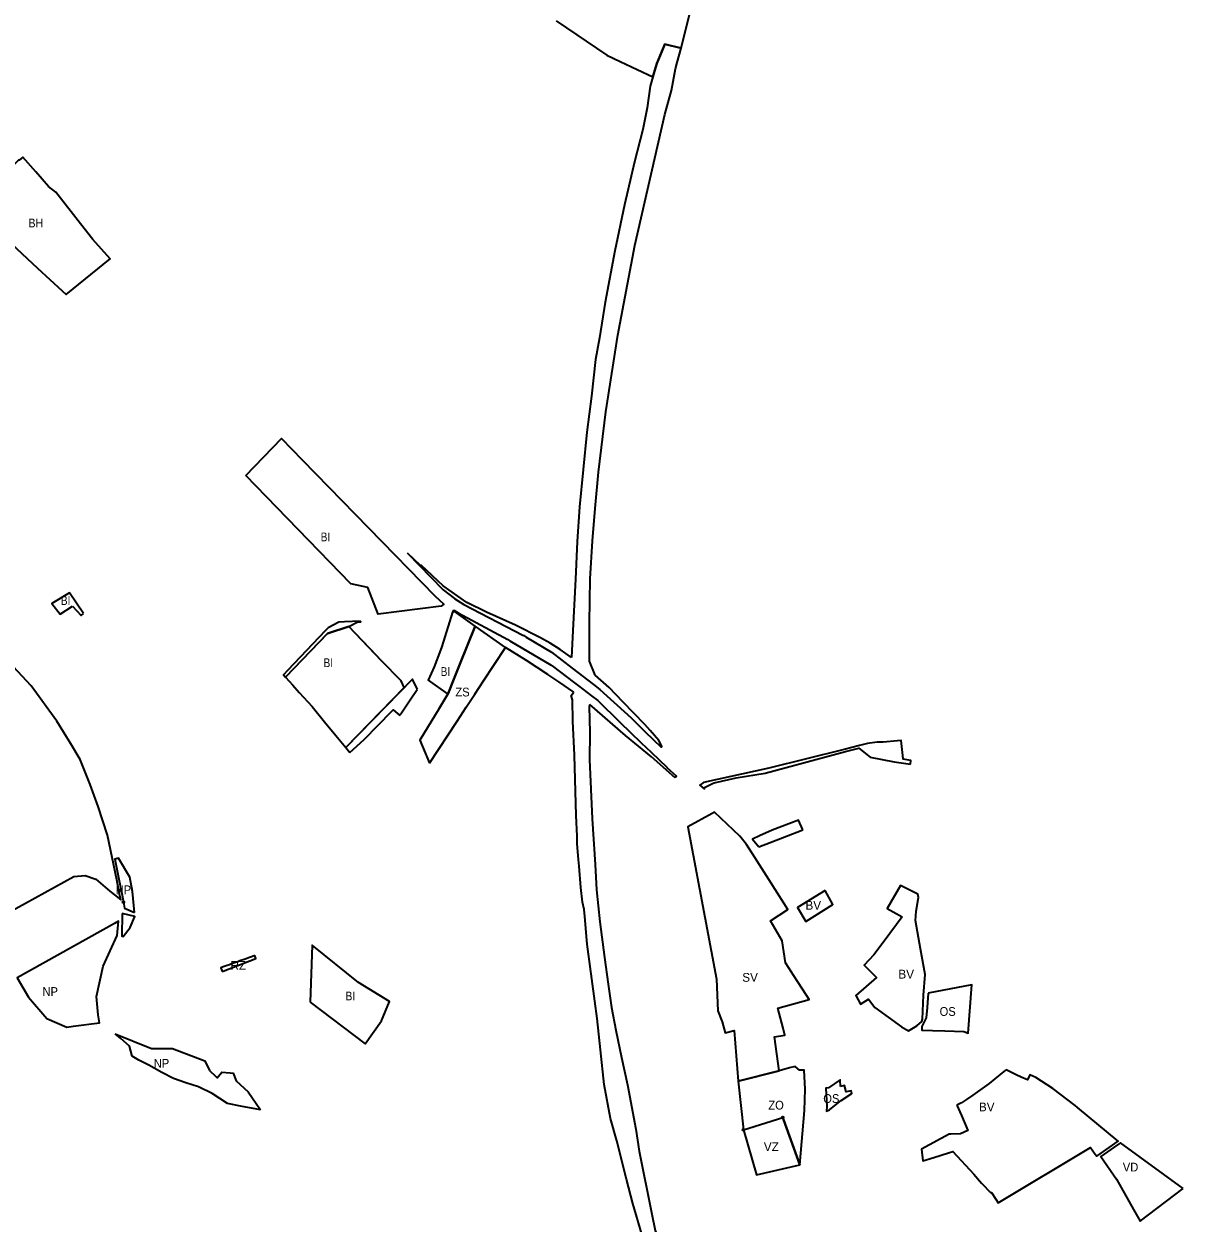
# Model space of a CAD drawing. Extents: x -650276 to -642489, y -1074311 to -1066658.
# Drawn here: x -646121 to -644537, y -1073213 to -1071573 of the extents above; entities that cross this region are included whole.
import ezdxf

# ---------------------------------------------------------------- set-up
doc = ezdxf.new("R2010")
doc.units = 0
doc.header["$LTSCALE"] = 4.8
doc.header["$PDMODE"] = 32
doc.header["$PDSIZE"] = 2.4
for name, color, linetype, lineweight in [('1', 7, 'Continuous', 35), ('15', 7, 'Continuous', 35), ('18', 7, 'Continuous', 35), ('2', 7, 'Continuous', 35), ('24', 7, 'Continuous', 35), ('3', 7, 'Continuous', 35), ('35', 7, 'Continuous', 35), ('36', 7, 'Continuous', 35), ('41', 7, 'Continuous', 35), ('42', 7, 'Continuous', 35), ('48', 7, 'Continuous', 35), ('6', 7, 'Continuous', 35), ('9', 7, 'Continuous', 35)]:
    doc.layers.add(name, color=color, linetype=linetype, lineweight=lineweight)
doc.layers.add('62', color=7, linetype='Continuous')
doc.layers.add('63', color=7, linetype='Continuous')

msp = doc.modelspace()

# ---------------------------------------------------------------- linework, layer by layer
at = {"layer": '1'}
msp.add_lwpolyline([(-646102.04, -1071906.4), (-646068.317, -1071937.555), (-646062.91, -1071942.55), (-646002.93, -1071893.984), (-646026.64, -1071867.44), (-646043.49, -1071845.87), (-646077.32, -1071802.59), (-646087, -1071795), (-646104.5, -1071774.86), (-646122.16, -1071754.78), (-646127.12, -1071759.15), (-646127.84, -1071758.53), (-646191.57, -1071821.44), (-646174.69, -1071838.69), (-646156.59, -1071856.53), (-646137.74, -1071873.31)], close=True, dxfattribs=at)
at = {"layer": '15'}
for points in [[(-645661.3, -1072388.74), (-645682.59, -1072389.76), (-645690.37, -1072390.13), (-645705, -1072398.19), (-645708.94, -1072402.11)], [(-645676.53, -1072396.16), (-645676.53, -1072396.16), (-645665.32, -1072390.32), (-645660.16, -1072389.95), (-645661.3, -1072388.74)], [(-645708.94, -1072402.11), (-645760.02, -1072455.94), (-645765.95, -1072462.03), (-645763.06, -1072465.26)], [(-645763.06, -1072465.26), (-645706.039, -1072405.769), (-645676.53, -1072396.16)], [(-645582.84, -1072481.71), (-645584.46, -1072478.58), (-645589.862, -1072468.109), (-645680.87, -1072561.42), (-645675.13, -1072568.36)], [(-645607.07, -1072517.61), (-645605.95, -1072515.95), (-645604.82, -1072514.3), (-645592.9, -1072496.52), (-645583.13, -1072482.13), (-645582.84, -1072481.71)], [(-645675.13, -1072568.36), (-645655.65, -1072550.62), (-645617.87, -1072512.12), (-645615.95, -1072510.16), (-645607.07, -1072517.61)], [(-644926.81, -1072552.51), (-644946.57, -1072554.22), (-644954.57, -1072554.43), (-644967.97, -1072556.17), (-644978.56, -1072558.74), (-644999.72, -1072564.24), (-645102.73, -1072589.74), (-645192.06, -1072609.19), (-645197.044, -1072612.821), (-645190.71, -1072618.6)], [(-644919.75, -1072572.43), (-644921.84, -1072552.03), (-644926.81, -1072552.51)], [(-645147.13, -1072602.79), (-645107.58, -1072596.47), (-644997.92, -1072567.23), (-644979.55, -1072562.44), (-644963.97, -1072574.57)], [(-644909.02, -1072584.28), (-644908.59, -1072579.51), (-644919.23, -1072577.46), (-644919.75, -1072572.43)], [(-644963.97, -1072574.57), (-644931.48, -1072581.26), (-644909.02, -1072584.28)], [(-645190.71, -1072618.6), (-645190.59, -1072616.28), (-645179.6, -1072610.94), (-645177.56, -1072609.89), (-645147.13, -1072602.79)], [(-645056.08, -1072674.07), (-645062.131, -1072660.856), (-645098.016, -1072674.425), (-645115.56, -1072682.406), (-645124.933, -1072686.721), (-645116.11, -1072697.15)], [(-645116.11, -1072697.15), (-645100.9, -1072691.31), (-645056.08, -1072674.07)]]:
    msp.add_lwpolyline(points, dxfattribs=at)
at = {"layer": '18'}
msp.add_lwpolyline([(-645144.37, -1073017.64), (-645088.62, -1073003.45), (-645095.04, -1072957.07), (-645080.61, -1072954.43), (-645083.13, -1072944.94), (-645090.34, -1072917.86), (-645047.42, -1072906.05), (-645050.6, -1072901.03), (-645069.55, -1072872.12), (-645071.87, -1072868.45), (-645079.81, -1072855.89), (-645084.47, -1072825.67), (-645100.27, -1072798.46), (-645076.66, -1072783.06), (-645099.58, -1072746.945), (-645121.96, -1072711.68), (-645133.26, -1072694.17), (-645142.1, -1072682.57), (-645176.757, -1072649.968), (-645180.05, -1072651.77), (-645213.34, -1072669.98), (-645174.13, -1072877.93), (-645172.28, -1072921.42), (-645166.48, -1072936.5), (-645162.379, -1072951.55), (-645149.84, -1072948.13)], close=True, dxfattribs=at)
at = {"layer": '2'}
msp.add_line((-645553.35, -1072508.1), (-645541.09, -1072487.98), dxfattribs=at)
for points in [[(-645817.219, -1072189.975), (-645768.649, -1072139.283), (-645740.45, -1072168.23), (-645559.34, -1072354.42), (-645546.82, -1072365.72), (-645550.41, -1072368.47), (-645636.37, -1072379.57), (-645650.78, -1072342.73), (-645674, -1072338), (-645789.298, -1072218.833)], [(-645729.36, -1072909.65), (-645654.16, -1072966.3), (-645632.23, -1072935.28), (-645620.92, -1072908.65), (-645663.52, -1072882.58), (-645726.9, -1072831.5)]]:
    msp.add_lwpolyline(points, close=True, dxfattribs=at)
for points in [[(-646039.16, -1072378.43), (-646058.64, -1072350.29), (-646082.55, -1072364.84), (-646071, -1072379.27), (-646054.43, -1072368.34)], [(-646054.43, -1072368.34), (-646042.65, -1072381.23), (-646039.16, -1072378.43)], [(-645541.09, -1072487.98), (-645533.15, -1072468.21), (-645524.87, -1072447.61), (-645503.98, -1072395.64), (-645532.75, -1072375.41), (-645535.05, -1072376.72), (-645549.6, -1072423.39), (-645551.54, -1072428.66), (-645559.92, -1072451.41), (-645568.38, -1072469.68), (-645541.56, -1072488.74)], [(-645632.1, -1072442.93), (-645676.53, -1072396.16), (-645706.039, -1072405.769), (-645763.06, -1072465.26), (-645753.128, -1072476.383), (-645744.38, -1072486.18), (-645726.95, -1072505.7), (-645709.92, -1072526.3), (-645694.51, -1072544.93), (-645680.87, -1072561.42), (-645600.883, -1072479.409)], [(-645632.1, -1072442.93), (-645638.82, -1072435.99), (-645676.53, -1072396.16), (-645706.039, -1072405.769), (-645763.06, -1072465.26), (-645753.128, -1072476.383)], [(-645600.945, -1072479.473), (-645605.17, -1072470.52), (-645632.1, -1072442.93)], [(-645753.128, -1072476.383), (-645744.38, -1072486.18), (-645726.95, -1072505.7), (-645709.92, -1072526.3)], [(-645709.92, -1072526.3), (-645694.51, -1072544.93), (-645680.87, -1072561.42), (-645600.945, -1072479.473)]]:
    msp.add_lwpolyline(points, dxfattribs=at)
at = {"layer": '24'}
for points in [[(-645393.34, -1071568.75), (-645324.17, -1071615.53), (-645324.17, -1071615.53), (-645305.78, -1071624.13), (-645282.54, -1071634.997), (-645261.094, -1071645.025), (-645255.662, -1071626.67), (-645248.786, -1071610.383), (-645244.81, -1071600.61), (-645222.48, -1071606.08), (-645222.48, -1071606.08), (-645211.27, -1071560.01)], [(-645222.48, -1071606.08), (-645244.81, -1071600.61), (-645248.786, -1071610.383), (-645255.662, -1071626.67)], [(-645222.48, -1071606.08), (-645244.81, -1071600.61), (-645248.786, -1071610.383), (-645255.662, -1071626.67)], [(-645339.904, -1072462.677), (-645347.551, -1072443.527), (-645347.677, -1072391.355), (-645346.62, -1072330.914), (-645343.458, -1072278.998), (-645339.908, -1072235.158), (-645335.367, -1072185.207), (-645325.498, -1072102.789), (-645309.01, -1071998.147), (-645285.617, -1071875.733), (-645244.798, -1071696.585), (-645235.793, -1071663.703), (-645230.436, -1071634.261), (-645227.905, -1071625.277), (-645222.48, -1071606.08)], [(-645339.904, -1072462.677), (-645347.551, -1072443.527), (-645347.677, -1072391.355), (-645346.62, -1072330.914), (-645343.458, -1072278.998), (-645339.908, -1072235.158), (-645335.367, -1072185.207), (-645325.498, -1072102.789), (-645309.01, -1071998.147), (-645285.617, -1071875.733), (-645244.798, -1071696.585), (-645235.793, -1071663.703), (-645230.436, -1071634.261), (-645227.905, -1071625.277), (-645222.48, -1071606.08)], [(-645255.662, -1071626.67), (-645261.094, -1071645.025), (-645264.841, -1071657.687), (-645269.077, -1071687.396), (-645274.868, -1071717.176), (-645286.175, -1071761.228), (-645300.076, -1071820.179), (-645313.153, -1071883.081), (-645326.343, -1071952.807)], [(-645255.662, -1071626.67), (-645261.094, -1071645.025), (-645264.841, -1071657.687), (-645269.077, -1071687.396), (-645274.868, -1071717.176), (-645286.175, -1071761.228), (-645300.076, -1071820.179), (-645313.153, -1071883.081)], [(-645313.153, -1071883.081), (-645326.343, -1071952.807), (-645334.118, -1072001.954), (-645339.455, -1072031.565), (-645344.819, -1072081.225), (-645351.358, -1072130.815), (-645361.317, -1072232.824), (-645364.435, -1072280.268), (-645366.951, -1072331.609), (-645370.624, -1072401.447), (-645372.228, -1072438.764)], [(-645326.343, -1071952.807), (-645334.118, -1072001.954), (-645339.455, -1072031.565), (-645344.819, -1072081.225), (-645351.358, -1072130.815), (-645361.317, -1072232.824), (-645364.435, -1072280.268), (-645366.951, -1072331.609), (-645370.624, -1072401.447), (-645372.228, -1072438.764)], [(-645372.228, -1072438.764), (-645387.894, -1072427.453), (-645401.441, -1072419.033), (-645414.631, -1072411.611), (-645448.831, -1072394.325), (-645488.64, -1072376.782), (-645515.437, -1072363.447), (-645547.593, -1072340.827), (-645577.33, -1072312.704), (-645579.217, -1072312.425), (-645596.405, -1072296.114)], [(-645596.405, -1072296.114), (-645564.4, -1072328.61), (-645547.72, -1072346.19), (-645532.07, -1072358.01), (-645531.65, -1072358.29), (-645528.27, -1072360.53), (-645519.57, -1072366.3), (-645438.64, -1072408.1)], [(-645372.228, -1072438.764), (-645387.894, -1072427.453), (-645401.441, -1072419.033), (-645414.631, -1072411.611), (-645448.831, -1072394.325), (-645488.64, -1072376.782), (-645515.437, -1072363.447), (-645547.593, -1072340.827), (-645577.33, -1072312.704), (-645579.217, -1072312.425), (-645596.405, -1072296.114)], [(-645596.405, -1072296.114), (-645564.4, -1072328.61), (-645547.72, -1072346.19), (-645532.07, -1072358.01), (-645531.65, -1072358.29), (-645528.27, -1072360.53), (-645519.57, -1072366.3), (-645438.64, -1072408.1)], [(-645462.646, -1072425.015), (-645503.98, -1072395.64), (-645532.75, -1072375.41), (-645534.3, -1072374.33), (-645533.08, -1072373.71)], [(-645533.08, -1072373.71), (-645527.33, -1072377.73), (-645459.31, -1072413.95), (-645456.52, -1072415.6), (-645400.12, -1072449.03), (-645396.94, -1072451.44), (-645370.226, -1072471.736)], [(-645438.64, -1072408.1), (-645437.6, -1072408.64), (-645434.19, -1072410.67), (-645399.77, -1072431.12), (-645371.356, -1072453.119), (-645342.284, -1072475.625)], [(-645438.64, -1072408.1), (-645437.6, -1072408.64), (-645434.19, -1072410.67), (-645399.77, -1072431.12), (-645371.356, -1072453.119), (-645342.284, -1072475.625), (-645333.62, -1072482.33), (-645290.76, -1072520.92)], [(-645369.364, -1072485.931), (-645389.731, -1072471.612), (-645404.64, -1072461.72), (-645433.91, -1072442.56), (-645462.646, -1072425.015)], [(-645370.226, -1072471.736), (-645362.81, -1072477.37), (-645345.079, -1072490.836)], [(-645290.76, -1072520.92), (-645271.74, -1072539.96), (-645249.9, -1072561.25), (-645248.967, -1072559.511), (-645252.768, -1072552.178), (-645265.009, -1072538.358), (-645272.276, -1072530.154), (-645302.303, -1072499.014), (-645320.805, -1072479.495), (-645339.904, -1072462.677)], [(-645290.76, -1072520.92), (-645271.74, -1072539.96), (-645249.9, -1072561.25), (-645248.967, -1072559.511), (-645252.768, -1072552.178), (-645265.009, -1072538.358), (-645272.276, -1072530.154), (-645302.303, -1072499.014), (-645320.805, -1072479.495), (-645339.904, -1072462.677)], [(-645364.524, -1072682.575), (-645366.022, -1072654.462), (-645368.173, -1072571.881), (-645370.755, -1072525.734), (-645370.928, -1072496.619), (-645372.72, -1072490.314), (-645369.364, -1072485.931)], [(-645345.079, -1072490.836), (-645336.33, -1072497.48), (-645306.46, -1072527.08), (-645276.93, -1072555.11), (-645263.7, -1072567.8), (-645242, -1072588.6), (-645241.87, -1072588.722), (-645228.96, -1072600.865), (-645230.845, -1072602.888)], [(-645342.284, -1072475.625), (-645333.62, -1072482.33), (-645290.76, -1072520.92)], [(-645347.292, -1072502.877), (-645348.253, -1072505.583), (-645347.214, -1072540.97), (-645347.795, -1072577.893), (-645344.152, -1072658.857), (-645339.96, -1072721.587), (-645338.023, -1072755.969), (-645333.718, -1072799.987)], [(-645230.845, -1072602.888), (-645263.217, -1072574.314), (-645298.498, -1072545.352), (-645347.292, -1072502.877)], [(-645357.272, -1072772.771), (-645359.76, -1072752.865), (-645361.874, -1072723.527), (-645362.708, -1072714.781), (-645364.786, -1072692.977), (-645364.524, -1072682.575)], [(-645271.518, -1073261.16), (-645272.747, -1073256.762), (-645275.269, -1073240.71), (-645276.125, -1073226.571), (-645288.647, -1073184.518), (-645297.395, -1073151.294), (-645310.558, -1073098.946), (-645319.052, -1073068.6), (-645327.554, -1073022.214), (-645332.517, -1072974.538), (-645337.34, -1072932.073), (-645340.345, -1072908.029), (-645350.822, -1072830.388), (-645354.019, -1072792.454), (-645355.121, -1072782.993), (-645357.272, -1072772.771)], [(-645333.718, -1072799.987), (-645327.091, -1072848.387), (-645322.284, -1072885.085), (-645317.65, -1072916.642)], [(-645317.65, -1072916.642), (-645311.772, -1072947.945), (-645304.24, -1072985.372), (-645295.788, -1073022.556)], [(-645295.788, -1073022.556), (-645284.269, -1073083.286), (-645279.878, -1073113.356), (-645262.388, -1073199.409), (-645257.842, -1073221.36), (-645247.051, -1073248.736), (-645239.9, -1073270.025), (-645226.847, -1073278.345), (-645227.199, -1073283.366), (-645227.744, -1073292.736)]]:
    msp.add_lwpolyline(points, dxfattribs=at)
at = {"layer": '3'}
for points in [[(-644902.18, -1072797.88), (-644901.35, -1072785.36), (-644898.29, -1072766.55), (-644899.2, -1072762.14), (-644922.88, -1072749.97), (-644940.8, -1072781.48), (-644920.46, -1072792.92)], [(-644920.46, -1072792.92), (-644945.2, -1072826.3), (-644959.24, -1072844.92), (-644972.28, -1072859.02), (-644955.49, -1072875.78), (-644983.93, -1072900.24), (-644977.16, -1072912.11), (-644966.57, -1072905.23), (-644957.79, -1072916.73), (-644921.18, -1072943.17), (-644911.87, -1072948.76), (-644900.2, -1072941.67), (-644893.77, -1072935.88), (-644892.86, -1072932.6), (-644891.2, -1072900.09), (-644889.11, -1072871.66), (-644895.32, -1072836.6), (-644902.18, -1072797.88)]]:
    msp.add_lwpolyline(points, dxfattribs=at)
for points in [[(-645025.61, -1072757.17), (-645063.6, -1072780.26), (-645051.94, -1072799.21), (-645015.02, -1072776.01)], [(-644845.72, -1073050.14), (-644839.57, -1073064.5), (-644830.81, -1073084.98), (-644840.89, -1073089.3), (-644853.8, -1073089.99), (-644856.4, -1073090.13), (-644894.15, -1073110.3), (-644892.14, -1073126.36), (-644877.32, -1073121.83), (-644856.97, -1073115.6), (-644851, -1073113.77), (-644822.62, -1073144.71), (-644811.96, -1073156.75), (-644799.26, -1073170.13), (-644798.38, -1073169.56), (-644792.59, -1073178.73), (-644789.31, -1073183.93), (-644663.17, -1073108.27), (-644656.56, -1073117.4), (-644654.61, -1073120.1), (-644649.7, -1073116.65), (-644625.26, -1073099.51), (-644680.69, -1073053.67), (-644684.09, -1073050.8), (-644714.42, -1073027.62), (-644714.42, -1073027.62), (-644737.88, -1073012.62), (-644745.73, -1073008.64), (-644748.95, -1073015.64), (-644757.73, -1073012.05), (-644764.69, -1073008.87), (-644778.38, -1073001.84), (-644781.52, -1073004.39), (-644793.743, -1073014.293), (-644801.54, -1073020.61), (-644824.08, -1073036.56), (-644832.7, -1073042.34), (-644839.47, -1073046.89)]]:
    msp.add_lwpolyline(points, close=True, dxfattribs=at)
at = {"layer": '35'}
for points in [[(-644536.62, -1073164.33), (-644622.03, -1073101.88), (-644630.58, -1073107.78), (-644648.95, -1073120.47), (-644627.53, -1073151.26)], [(-644627.53, -1073151.26), (-644604.13, -1073193), (-644595.18, -1073208.98), (-644536.62, -1073164.33)]]:
    msp.add_lwpolyline(points, dxfattribs=at)
at = {"layer": '36'}
msp.add_lwpolyline([(-645137.5, -1073083.97), (-645119.34, -1073145.61), (-645060.1, -1073131.68), (-645082.6, -1073069.93), (-645083.681, -1073066.962)], dxfattribs=at)
for p in [(-645083.681, -1073066.962), (-645137.5, -1073083.97)]:
    msp.add_point(p, dxfattribs=at)
at = {"layer": '41'}
msp.add_line((-645566.54, -1072582.88), (-645528.81, -1072525.54), dxfattribs=at)
msp.add_lwpolyline([(-645528.81, -1072525.54), (-645516.37, -1072506.64), (-645504.48, -1072488.58), (-645492.61, -1072470.54), (-645462.65, -1072425.01), (-645503.98, -1072395.64), (-645524.87, -1072447.61), (-645533.15, -1072468.21), (-645541.09, -1072487.98), (-645553.35, -1072508.1), (-645579.76, -1072551.45), (-645575.9, -1072560.13), (-645566.54, -1072582.88)], dxfattribs=at)
at = {"layer": '42'}
msp.add_lwpolyline([(-645054.12, -1073057.62), (-645052.94, -1073028.58), (-645054.44, -1073002.54), (-645060.95, -1073002.68), (-645066.66, -1072997.3), (-645074.333, -1072999.365), (-645088.62, -1073003.45), (-645144.37, -1073017.64), (-645137.5, -1073083.97), (-645083.681, -1073066.962), (-645082.6, -1073069.93), (-645060.1, -1073131.68)], close=True, dxfattribs=at)
at = {"layer": '48'}
for points in [[(-646171.72, -1072803.51), (-646052.58, -1072737.82), (-646037.23, -1072736.38), (-646022.4, -1072741.58), (-646003.22, -1072757.85), (-645988.43, -1072769.93), (-645990.04, -1072761.78), (-645993.89, -1072742.23), (-646006.66, -1072681.4), (-646019.16, -1072642.35), (-646030.17, -1072612.31), (-646043.87, -1072578.12), (-646056.42, -1072556.49), (-646075.82, -1072525.54), (-646110.61, -1072477.49), (-646153.49, -1072431.54)], [(-645969.46, -1072787.03), (-645972.31, -1072758.48), (-645975.86, -1072738.61), (-645991.31, -1072712.86), (-645996.31, -1072714.11), (-645990.95, -1072741.65), (-645987.1, -1072761.2), (-645984.79, -1072772.91)], [(-645984.79, -1072772.91), (-645983.22, -1072780.88), (-645969.46, -1072787.03)], [(-645986.24, -1072788.33), (-645986.71, -1072819.26), (-645986.71, -1072819.26)], [(-645975.3, -1072807.37), (-645969.01, -1072792.28), (-645986.24, -1072788.33)], [(-645986.71, -1072819.26), (-645986.71, -1072819.26), (-645985.19, -1072819.72), (-645975.3, -1072807.37)], [(-645972.6, -1072983.41), (-645976.48, -1072969.55), (-645988.49, -1072959.28), (-645996.2, -1072952.69)], [(-645996.2, -1072952.69), (-645946.4, -1072973.05), (-645917.53, -1072972.93), (-645873.3, -1072989.79), (-645866.93, -1073002.72)], [(-645863.39, -1073034.25), (-645882.07, -1073025.22), (-645899.35, -1073019.65), (-645916.47, -1073014.03), (-645932.44, -1073005.5), (-645949.85, -1072995.57), (-645962.81, -1072989.45), (-645963.77, -1072989), (-645972.6, -1072983.41)], [(-645866.93, -1073002.72), (-645858.82, -1073010.74), (-645856.46, -1073013.07), (-645850.37, -1073005.42), (-645838.89, -1073006.18)], [(-645838.89, -1073006.18), (-645834.9, -1073006.45), (-645830.6, -1073016.92), (-645814.27, -1073032.11), (-645797.32, -1073056.62)], [(-645797.32, -1073056.62), (-645824.93, -1073051.83), (-645842.53, -1073048.19), (-645863.39, -1073034.25)]]:
    msp.add_lwpolyline(points, dxfattribs=at)
msp.add_lwpolyline([(-645993.47, -1072818.44), (-645991.37, -1072798.84), (-645996.8, -1072801.88), (-646129.91, -1072876.24), (-646114.5, -1072902.8), (-646089.39, -1072931.92), (-646062.04, -1072943.58), (-646053.287, -1072942.399), (-646017.65, -1072937.59), (-646019.21, -1072926.91), (-646021.64, -1072901.6), (-646012.37, -1072860.3)], close=True, dxfattribs=at)
msp.add_point((-645984.79, -1072772.91), dxfattribs=at)
at = {"layer": '6'}
for points in [[(-645849.703, -1072867.622), (-645848.52, -1072867.16), (-645803.84, -1072849.72), (-645805.159, -1072845.994)], [(-645805.159, -1072845.994), (-645808.177, -1072847.063), (-645811.148, -1072848.124), (-645813.978, -1072849.124), (-645816.948, -1072850.184), (-645819.779, -1072851.184), (-645822.726, -1072852.233), (-645825.527, -1072853.233), (-645828.409, -1072854.254), (-645834.208, -1072856.314)], [(-645834.208, -1072856.314), (-645837.027, -1072857.313), (-645839.908, -1072858.343), (-645842.74, -1072859.344), (-645845.619, -1072860.364), (-645848.628, -1072861.433), (-645851.48, -1072862.586), (-645850.187, -1072866.251), (-645850.17, -1072866.3), (-645849.705, -1072867.618), (-645849.703, -1072867.622)]]:
    msp.add_lwpolyline(points, dxfattribs=at)
at = {"layer": '9'}
for points in [[(-644884.712, -1072897.147), (-644886.418, -1072916.953), (-644887.44, -1072930.94), (-644893.37, -1072942.61), (-644893.59, -1072947.97), (-644878.86, -1072948.42), (-644861.93, -1072948.94), (-644835.99, -1072949.74), (-644830.25, -1072951.9), (-644825.25, -1072885.96)], [(-645004.82, -1073024.63), (-645005.31, -1073015.68), (-645021.1, -1073026.69), (-645024.71, -1073026.95), (-645023.6, -1073052.12), (-645023.88, -1073058.37), (-645019.57, -1073056.46), (-645007.99, -1073047.31), (-645003.78, -1073043.96), (-644989.34, -1073034.58), (-644990.25, -1073030.54), (-644997.09, -1073032.21), (-644999.23, -1073023.29)]]:
    msp.add_lwpolyline(points, close=True, dxfattribs=at)

# ---------------------------------------------------------------- texts
at = {"layer": '62'}
for s, width, p in [('BH', 0.9, (-646114.48, -1071850.818)), ('BI', 0.85, (-645715.06, -1072279.771)), ('BI', 0.85, (-645711.104, -1072451.727)), ('BI', 0.85, (-645551.06, -1072463.771)), ('ZS', 0.95, (-645531.06, -1072491.771)), ('NP', 0.95, (-646095.335, -1072901.048)), ('BI', 0.85, (-645681, -1072907.167)), ('OS', 0.95, (-644869.265, -1072928.272)), ('NP', 0.95, (-645943.335, -1072999.048)), ('ZO', 0.95, (-645103.327, -1073056.309)), ('OS', 0.95, (-645028.265, -1073047.272)), ('VD', 0.95, (-644618.892, -1073140.939))]:
    msp.add_text(s, height=12, dxfattribs=dict(at, width=width)).set_placement(p)
for s, p in [('BV', (-645052.614, -1072783.26)), ('RZ', (-645838.415, -1072865.224)), ('BV', (-644925.614, -1072877.26)), ('SV', (-645139.013, -1072881.667)), ('BV', (-644815.563, -1073058.759)), ('VZ', (-645109.496, -1073113.102))]:
    msp.add_text(s, height=12, dxfattribs=at).set_placement(p)
at = {"layer": '63'}
for s, width, p in [('BI', 0.85, (-646070.104, -1072366.727)), ('NP', 0.95, (-645995.335, -1072762.048))]:
    msp.add_text(s, height=12, dxfattribs=dict(at, width=width)).set_placement(p)

doc.saveas('drawing.dxf')
